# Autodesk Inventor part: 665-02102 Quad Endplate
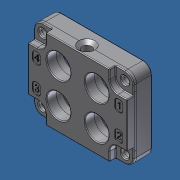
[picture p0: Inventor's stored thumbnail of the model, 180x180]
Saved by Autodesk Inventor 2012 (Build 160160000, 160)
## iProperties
Created: 2013-10
Part Number: 665-02102 Quad Endplate
Material: Default
Document SubType Name: Modeling
Designer: Admin
Density: 1 g/cm^3
Author: Admin
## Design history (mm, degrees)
node "665-02102 Quad Endplate1"
node "Base1"
body "Solid1"
